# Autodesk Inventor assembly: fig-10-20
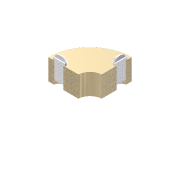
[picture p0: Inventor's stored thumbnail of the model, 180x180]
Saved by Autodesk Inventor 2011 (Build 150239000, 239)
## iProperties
Shininess: 64.0
Angle Display Precision: 2
Document Length Units: 11269
Document Angle Units: 11279
Document Time Units: 11290
Document Mass Units: 11283
Document Length Units Precision: 3
Document Angle Units Precision: 2
Created: 2002-02
Part Number: fig-10-20
Document SubType Name: Assembly
Designer: ***
Density: 0.0
Volumn: 0.0
Area: 0.0
PropertySet Name: Model Information
Control State: 0
Master: False
Checked Out: False
Author: ***
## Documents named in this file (3)
- C:\Users\CADSoft\Desktop\part files\c10-inv-2011-prt\fig-10-20.iam
- C:\Users\CADSoft\Desktop\inventor\c10-inv-2010-prt\c10\Screw.ipt
- C:\Users\CADSoft\Desktop\inventor\c10-inv-2010-prt\c10\test.ipt
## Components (6 placed, 2 different names)
1. test:1 — Insert:1, Insert:2
2. test:2 — Insert:1
3. Screw:1 — Angle:1, Insert:2
4. Screw:11
5. Screw:12
6. Screw:13
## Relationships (3: Insert 2, Angle 1)
- Insert:1: test:1 ↔ test:2
- Angle:1: Screw:1
- Insert:2: test:1 ↔ Screw:1
